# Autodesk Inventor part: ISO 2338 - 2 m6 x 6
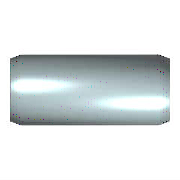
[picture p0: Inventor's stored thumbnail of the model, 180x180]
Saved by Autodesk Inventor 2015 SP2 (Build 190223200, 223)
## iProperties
Created: 2014-02
Part Number: ISO 2338 - 2 m6 x 6
Material: Edelstahl, austenitisch
Description: Zylinderstift
Document SubType Name: Modeling
Standard: ISO 2338
Designer: ryll
Standards Organization: DIN
Language: de-DE
Size Designation: 2 m6 x 6
Categories: <MemberInstance><Categories><Category DisplayName="Verbindungselemente" InternalName="e4da775c-781d-43d5-af7c-5136215cf5a6" Mnemonic="FSTN"><Category DisplayNam
Density: 8 g/cm^3
Appearance: Halbpoliert
IsCustomPart: 0
Author: ryll
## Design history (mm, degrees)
sketch "Skizze"
  geometry: C1 r 1 at (0, 0); 1 further point
  constraints: 1 centre point, 1 coincident
  dimensions: "d1" = 2 diameter of C1 (= NND)
extrude "Körper" new body sketch "Skizze" distance "d2" = 6 (= NLG); taper "d3" = 0 deg
body "Solid1"
chamfer "Fase1" distance "d4" = 0.35 (= PHH); stored, may be unused: angle "d5" = 15 deg (= FAWI), second distance "d11" = 0.35 (= PHH)
chamfer "Fase2" distance "d8" = 0.35 (= PHH); stored, may be unused: angle "d9" = 15 deg (= FAWI), second distance "d12" = 0.35 (= PHH)
other parameters: "NND" = 2 [user parameter; used in 1 equation term], "NLG" = 6 [user parameter; used in 1 equation term], "PHH" = 0.35 [user parameter; used in 4 equation terms], "FAWI" = 15 deg [user parameter; used in 2 equation terms], "d13" = 0, "d15" = 0, "d16" = 0, "KAH" = 0 [user parameter]
